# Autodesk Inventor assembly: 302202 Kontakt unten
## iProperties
Created: 2006-12
Part Number: 302202 Kontakt unten
Cost Center: 0 kg
Document SubType Name: Assembly
Designer: Martin
Authority: 0 mm^3
Mass: 10656 g
Surface Area: 2336.71 cm^2
Volume: 1539.55 cm^3
Density: 6.92146 g/cm^3
SaveDate: 2004-08-02
SaveTime: 16:43
TotalMass: 0 kg
TotalVolume: 0 mm^3
Author: Martin
